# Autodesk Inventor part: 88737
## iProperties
Created: 2005-11
Part Number: 88737
Material: 1.4301 X5CrNi10-10 A2
Description: T-Stück  DN 160 ISO-K
Document SubType Name: Modellieren
Designer: Mittelmeyer
Manufacturer: Standard
Standards Organization: Custom
Vendor: LEYBOLD
Author: Mittelmeyer
Comments: LEYBOLD
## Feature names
1. Extrusion2
2. Extrusion3
3. Extrusion4
4. Drehung1 [Revolution]
5. Bohrung1 [Hole]
6. Runde Anordnung1 [Circular Pattern]
7. Extrusion5
